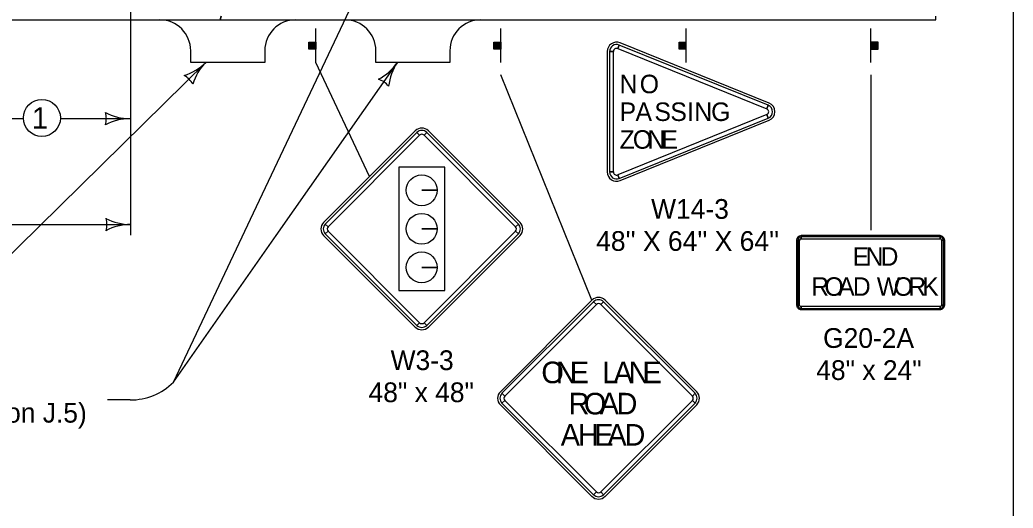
# Model space of a CAD drawing. Extents: x -2134934 to -2122394, y -2139046 to -2137036.
# Drawn here: x -2132604 to -2131799, y -2138064 to -2137668 of the extents above; entities that cross this region are included whole.
import ezdxf

# ---------------------------------------------------------------- set-up
doc = ezdxf.new("R2010")
doc.units = 0
for name, color, linetype in [('Barrier', 7, 'Continuous'), ('BridgeSuperStructureExisting', 7, 'Continuous'), ('Default', 7, 'Continuous'), ('DsnShtPlotIdentification', 7, 'Continuous'), ('DsnShtPlotShape', 7, 'Continuous')]:
    doc.layers.add(name, color=color, linetype=linetype)

msp = doc.modelspace()

# ---------------------------------------------------------------- linework, layer by layer
at = {"layer": 'Barrier'}
for p, q in [((-2132119.84, -2137691.45), (-2132118.67, -2137688.56)), ((-2131997.15, -2137735.69), (-2132117.97, -2137686.82)), ((-2132128.28, -2137693.77), (-2132128.28, -2137791.52)), ((-2132126.41, -2137693.77), (-2132123.28, -2137693.77)), ((-2131997.85, -2137737.43), (-2131999.02, -2137740.33)), ((-2131999.02, -2137744.96), (-2131997.85, -2137747.86)), ((-2132117.97, -2137798.48), (-2131997.15, -2137749.6)), ((-2132283.85, -2137758.12), (-2132358.09, -2137832.37)), ((-2132282.52, -2137759.45), (-2132280.31, -2137761.66)), ((-2132276.78, -2137761.66), (-2132274.57, -2137759.45)), ((-2132198.99, -2137832.37), (-2132273.24, -2137758.12)), ((-2132123.28, -2137791.52), (-2132126.41, -2137791.52)), ((-2132118.67, -2137796.74), (-2132119.84, -2137793.84)), ((-2132266.14, -2137806.34), (-2132278.64, -2137806.34)), ((-2132278.64, -2137806.34), (-2132266.14, -2137806.34)), ((-2132354.56, -2137835.9), (-2132356.77, -2137833.69)), ((-2132200.32, -2137833.69), (-2132202.53, -2137835.9)), ((-2132358.09, -2137842.98), (-2132283.85, -2137917.22)), ((-2132356.77, -2137841.65), (-2132354.56, -2137839.44)), ((-2132266.14, -2137837.59), (-2132278.64, -2137837.59)), ((-2132278.64, -2137837.59), (-2132266.14, -2137837.59)), ((-2132273.24, -2137917.22), (-2132198.99, -2137842.98)), ((-2132202.53, -2137839.44), (-2132200.32, -2137841.65)), ((-2131858.66, -2137843.14), (-2131971.16, -2137843.14)), ((-2131971.16, -2137845.64), (-2131971.16, -2137844.08)), ((-2131858.66, -2137844.08), (-2131858.66, -2137845.64)), ((-2131974.91, -2137846.89), (-2131974.91, -2137899.39)), ((-2131973.97, -2137846.89), (-2131972.41, -2137846.89)), ((-2131857.41, -2137846.89), (-2131855.85, -2137846.89)), ((-2131854.91, -2137899.39), (-2131854.91, -2137846.89)), ((-2132266.14, -2137868.84), (-2132278.64, -2137868.84)), ((-2132278.64, -2137868.84), (-2132266.14, -2137868.84)), ((-2132140.68, -2137895.4), (-2132214.93, -2137969.64)), ((-2132139.36, -2137896.72), (-2132137.15, -2137898.93)), ((-2132133.61, -2137898.93), (-2132131.4, -2137896.72)), ((-2132055.83, -2137969.64), (-2132130.08, -2137895.4)), ((-2131972.41, -2137899.39), (-2131973.97, -2137899.39)), ((-2131971.16, -2137902.2), (-2131971.16, -2137900.64)), ((-2131858.66, -2137900.64), (-2131858.66, -2137902.2)), ((-2131855.85, -2137899.39), (-2131857.41, -2137899.39)), ((-2131971.16, -2137903.14), (-2131858.66, -2137903.14)), ((-2132280.31, -2137913.69), (-2132282.52, -2137915.9)), ((-2132274.57, -2137915.9), (-2132276.78, -2137913.69)), ((-2132211.4, -2137973.18), (-2132213.6, -2137970.97)), ((-2132057.16, -2137970.97), (-2132059.37, -2137973.18)), ((-2132214.93, -2137980.25), (-2132140.68, -2138054.5)), ((-2132213.6, -2137978.92), (-2132211.4, -2137976.71)), ((-2132130.08, -2138054.5), (-2132055.83, -2137980.25)), ((-2132059.37, -2137976.71), (-2132057.16, -2137978.92)), ((-2132137.15, -2138050.96), (-2132139.36, -2138053.17)), ((-2132131.4, -2138053.17), (-2132133.61, -2138050.96))]:
    msp.add_line(p, q, dxfattribs=at)
for points in [[(-2131997.85, -2137737.43), (-2132118.67, -2137688.56), (-2132119.84, -2137691.45), (-2131999.02, -2137740.33), (-2131997.85, -2137737.43)], [(-2132126.41, -2137693.77), (-2132126.41, -2137791.52), (-2132123.28, -2137791.52), (-2132123.28, -2137693.77), (-2132126.41, -2137693.77)], [(-2132118.67, -2137796.74), (-2131997.85, -2137747.86), (-2131999.02, -2137744.96), (-2132119.84, -2137793.84), (-2132118.67, -2137796.74)], [(-2132282.52, -2137759.45), (-2132356.77, -2137833.69), (-2132354.56, -2137835.9), (-2132280.31, -2137761.66), (-2132282.52, -2137759.45)], [(-2132200.32, -2137833.69), (-2132274.57, -2137759.45), (-2132276.78, -2137761.66), (-2132202.53, -2137835.9), (-2132200.32, -2137833.69)], [(-2132259.81, -2137787.73), (-2132297.28, -2137787.73), (-2132297.28, -2137887.62), (-2132259.81, -2137887.62), (-2132259.81, -2137787.73)], [(-2132356.77, -2137841.65), (-2132282.52, -2137915.9), (-2132280.31, -2137913.69), (-2132354.56, -2137839.44), (-2132356.77, -2137841.65)], [(-2132274.57, -2137915.9), (-2132200.32, -2137841.65), (-2132202.53, -2137839.44), (-2132276.78, -2137913.69), (-2132274.57, -2137915.9)], [(-2131858.66, -2137844.08), (-2131971.16, -2137844.08), (-2131971.16, -2137845.64), (-2131858.66, -2137845.64), (-2131858.66, -2137844.08)], [(-2131973.97, -2137846.89), (-2131973.97, -2137899.39), (-2131972.41, -2137899.39), (-2131972.41, -2137846.89), (-2131973.97, -2137846.89)], [(-2131855.85, -2137899.39), (-2131855.85, -2137846.89), (-2131857.41, -2137846.89), (-2131857.41, -2137899.39), (-2131855.85, -2137899.39)], [(-2132139.36, -2137896.72), (-2132213.6, -2137970.97), (-2132211.4, -2137973.18), (-2132137.15, -2137898.93), (-2132139.36, -2137896.72)], [(-2132057.16, -2137970.97), (-2132131.4, -2137896.72), (-2132133.61, -2137898.93), (-2132059.37, -2137973.18), (-2132057.16, -2137970.97)], [(-2131971.16, -2137902.2), (-2131858.66, -2137902.2), (-2131858.66, -2137900.64), (-2131971.16, -2137900.64), (-2131971.16, -2137902.2)], [(-2132213.6, -2137978.92), (-2132139.36, -2138053.17), (-2132137.15, -2138050.96), (-2132211.4, -2137976.71), (-2132213.6, -2137978.92)], [(-2132131.4, -2138053.17), (-2132057.16, -2137978.92), (-2132059.37, -2137976.71), (-2132133.61, -2138050.96), (-2132131.4, -2138053.17)]]:
    msp.add_lwpolyline(points, close=True, dxfattribs=at)
for centre in [(-2132278.64, -2137806.34), (-2132278.64, -2137837.59), (-2132278.64, -2137868.84)]:
    msp.add_circle(centre, 12.5, dxfattribs=at)
for centre, radius, start, end in [((-2132120.78, -2137693.77), 7.5, 67.97571, 179.99985), ((-2132120.78, -2137693.77), 5.62, 67.97571, 179.99985), ((-2132120.78, -2137693.77), 2.5, 67.97571, 179.99985), ((-2131999.96, -2137742.65), 2.5, 292.02456, 67.97541), ((-2131999.96, -2137742.65), 5.62, 292.02456, 67.97541), ((-2131999.96, -2137742.65), 7.5, 292.02456, 67.97598), ((-2132278.54, -2137763.43), 7.5, 44.99999, 134.99974), ((-2132278.54, -2137763.43), 5.62, 44.99999, 134.99974), ((-2132278.54, -2137763.43), 2.5, 44.99999, 134.99974), ((-2132120.78, -2137791.52), 7.5, 179.99985, 292.02456), ((-2132120.78, -2137791.52), 5.62, 179.99985, 292.02456), ((-2132120.78, -2137791.52), 2.5, 179.99985, 292.02456), ((-2132352.79, -2137837.67), 7.5, 134.99974, 224.99995), ((-2132352.79, -2137837.67), 5.62, 134.99974, 224.99995), ((-2132352.79, -2137837.67), 2.5, 134.99974, 224.99995), ((-2132204.3, -2137837.67), 2.5, 315.00016, 44.9998), ((-2132204.3, -2137837.67), 5.62, 315.00016, 44.9998), ((-2132204.3, -2137837.67), 7.5, 315.00016, 44.9998), ((-2131971.16, -2137846.89), 3.75, 90.00021, 179.99985), ((-2131971.16, -2137846.89), 2.81, 90.00021, 179.99985), ((-2131858.66, -2137846.89), 3.75, 0, 90.00021), ((-2131858.66, -2137846.89), 2.81, 0, 90.00021), ((-2131971.16, -2137846.89), 1.25, 90.00021, 179.99985), ((-2131858.66, -2137846.89), 1.25, 0, 90.00021), ((-2132135.38, -2137900.7), 7.5, 44.99999, 134.99974), ((-2132135.38, -2137900.7), 5.62, 44.99999, 134.99974), ((-2132135.38, -2137900.7), 2.5, 44.99999, 134.99974), ((-2131971.16, -2137899.39), 3.75, 179.99985, 270.00006), ((-2131971.16, -2137899.39), 2.81, 179.99985, 270.00006), ((-2131971.16, -2137899.39), 1.25, 179.99985, 270.00006), ((-2131858.66, -2137899.39), 3.75, 270.00006, 0.00027), ((-2131858.66, -2137899.39), 2.81, 270.00006, 0.00027), ((-2131858.66, -2137899.39), 1.25, 270.00006, 0.00027), ((-2132278.54, -2137911.92), 7.5, 224.99995, 315.00016), ((-2132278.54, -2137911.92), 5.62, 224.99995, 315.00016), ((-2132278.54, -2137911.92), 2.5, 224.99995, 315.00016), ((-2132209.63, -2137974.95), 7.5, 134.99974, 224.99995), ((-2132209.63, -2137974.95), 5.62, 134.99974, 224.99995), ((-2132209.63, -2137974.95), 2.5, 134.99974, 224.99995), ((-2132061.14, -2137974.95), 2.5, 315.00016, 44.9998), ((-2132061.14, -2137974.95), 5.62, 315.00016, 44.9998), ((-2132061.14, -2137974.95), 7.5, 315.00016, 44.9998), ((-2132135.38, -2138049.19), 5.62, 224.99995, 315.00016), ((-2132135.38, -2138049.19), 2.5, 224.99995, 315.00016), ((-2132135.38, -2138049.19), 7.5, 224.99995, 315.00016)]:
    msp.add_arc(centre, radius, start, end, dxfattribs=at)
at = {"layer": 'BridgeSuperStructureExisting'}
for p, q in [((-2132414.88, -2137824.64), (-2132275.76, -2137530.07)), ((-2132514.45, -2137842.77), (-2132514.45, -2137605.16)), ((-2132490.81, -2137668.16), (-2132380.81, -2137668.16)), ((-2132364.45, -2137702.66), (-2132364.45, -2137675.16)), ((-2132340.81, -2137668.16), (-2132230.81, -2137668.16)), ((-2132214.45, -2137702.66), (-2132214.45, -2137675.16)), ((-2132064.45, -2137702.66), (-2132064.45, -2137675.16)), ((-2131914.64, -2137702.66), (-2131914.64, -2137675.16)), ((-2132369.77, -2137691.8), (-2132369.77, -2137686.21)), ((-2132369.45, -2137686.21), (-2132369.45, -2137691.8)), ((-2132369.23, -2137691.8), (-2132369.23, -2137686.21)), ((-2132368.91, -2137686.21), (-2132368.91, -2137691.8)), ((-2132368.68, -2137691.8), (-2132368.7, -2137686.21)), ((-2132368.27, -2137686.21), (-2132368.25, -2137691.8)), ((-2132368.05, -2137691.8), (-2132368.05, -2137686.21)), ((-2132367.62, -2137686.21), (-2132367.62, -2137691.8)), ((-2132367.24, -2137691.8), (-2132367.24, -2137686.21)), ((-2132366.92, -2137686.21), (-2132366.9, -2137691.8)), ((-2132366.7, -2137691.8), (-2132366.7, -2137686.21)), ((-2132366.43, -2137686.21), (-2132366.43, -2137691.8)), ((-2132366.1, -2137691.8), (-2132366.1, -2137686.21)), ((-2132365.89, -2137686.21), (-2132365.89, -2137691.8)), ((-2132365.67, -2137691.8), (-2132365.67, -2137686.21)), ((-2132365.4, -2137686.21), (-2132365.4, -2137691.8)), ((-2132365.14, -2137691.8), (-2132365.14, -2137686.21)), ((-2132364.86, -2137686.21), (-2132364.86, -2137691.8)), ((-2132219.77, -2137691.8), (-2132219.77, -2137686.21)), ((-2132219.45, -2137686.21), (-2132219.45, -2137691.8)), ((-2132219.23, -2137691.8), (-2132219.23, -2137686.21)), ((-2132218.91, -2137686.21), (-2132218.91, -2137691.8)), ((-2132218.69, -2137691.8), (-2132218.7, -2137686.21)), ((-2132218.27, -2137686.21), (-2132218.25, -2137691.8)), ((-2132218.05, -2137691.8), (-2132218.05, -2137686.21)), ((-2132217.62, -2137686.21), (-2132217.62, -2137691.8)), ((-2132217.24, -2137691.8), (-2132217.24, -2137686.21)), ((-2132216.92, -2137686.21), (-2132216.9, -2137691.8)), ((-2132216.7, -2137691.8), (-2132216.7, -2137686.21)), ((-2132216.43, -2137686.21), (-2132216.43, -2137691.8)), ((-2132216.1, -2137691.8), (-2132216.1, -2137686.21)), ((-2132215.89, -2137686.21), (-2132215.89, -2137691.8)), ((-2132215.67, -2137691.8), (-2132215.67, -2137686.21)), ((-2132215.4, -2137686.21), (-2132215.4, -2137691.8)), ((-2132215.14, -2137691.8), (-2132215.14, -2137686.21)), ((-2132214.86, -2137686.21), (-2132214.86, -2137691.8)), ((-2132069.77, -2137691.8), (-2132069.77, -2137686.21)), ((-2132069.45, -2137686.21), (-2132069.45, -2137691.8)), ((-2132069.23, -2137691.8), (-2132069.23, -2137686.21)), ((-2132068.91, -2137686.21), (-2132068.91, -2137691.8)), ((-2132068.69, -2137691.8), (-2132068.7, -2137686.21)), ((-2132068.27, -2137686.21), (-2132068.25, -2137691.8)), ((-2132068.05, -2137691.8), (-2132068.05, -2137686.21)), ((-2132067.62, -2137686.21), (-2132067.62, -2137691.8)), ((-2132067.24, -2137691.8), (-2132067.24, -2137686.21)), ((-2132066.92, -2137686.21), (-2132066.9, -2137691.8)), ((-2132066.7, -2137691.8), (-2132066.7, -2137686.21)), ((-2132066.43, -2137686.21), (-2132066.43, -2137691.8)), ((-2132066.1, -2137691.8), (-2132066.1, -2137686.21)), ((-2132065.89, -2137686.21), (-2132065.89, -2137691.8)), ((-2132065.67, -2137691.8), (-2132065.67, -2137686.21)), ((-2132065.4, -2137686.21), (-2132065.4, -2137691.8)), ((-2132065.14, -2137691.8), (-2132065.14, -2137686.21)), ((-2132064.86, -2137686.21), (-2132064.86, -2137691.8)), ((-2131914.22, -2137686.21), (-2131914.22, -2137691.8)), ((-2131913.94, -2137691.8), (-2131913.94, -2137686.21)), ((-2131913.68, -2137686.21), (-2131913.68, -2137691.8)), ((-2131913.42, -2137691.8), (-2131913.42, -2137686.21)), ((-2131913.19, -2137686.21), (-2131913.19, -2137691.8)), ((-2131912.99, -2137691.8), (-2131912.99, -2137686.21)), ((-2131912.65, -2137686.21), (-2131912.65, -2137691.8)), ((-2131912.39, -2137691.8), (-2131912.39, -2137686.21)), ((-2131912.16, -2137686.21), (-2131912.18, -2137691.8)), ((-2131911.84, -2137691.8), (-2131911.84, -2137686.21)), ((-2131911.47, -2137686.21), (-2131911.47, -2137691.8)), ((-2131911.04, -2137691.8), (-2131911.04, -2137686.21)), ((-2131910.81, -2137686.21), (-2131910.83, -2137691.8)), ((-2131910.4, -2137691.8), (-2131910.38, -2137686.21)), ((-2131910.17, -2137686.21), (-2131910.17, -2137691.8)), ((-2131909.85, -2137691.8), (-2131909.85, -2137686.21)), ((-2131909.63, -2137686.21), (-2131909.63, -2137691.8)), ((-2131909.31, -2137691.8), (-2131909.31, -2137686.21)), ((-2132641.72, -2137887.94), (-2132453.59, -2137702.65)), ((-2132396.52, -2137843), (-2132298.35, -2137702.65)), ((-2132320.97, -2137795.25), (-2132364.45, -2137702.66)), ((-2132140.68, -2137895.4), (-2132214.45, -2137712.66)), ((-2131914.45, -2137838.71), (-2131914.45, -2137712.66)), ((-2132714.94, -2137748.23), (-2132601.37, -2137748.23)), ((-2132571.38, -2137748.23), (-2132514.94, -2137748.23)), ((-2132479.75, -2137962), (-2132414.88, -2137824.64)), ((-2132739.17, -2137834.09), (-2132514.45, -2137834.09)), ((-2132479.75, -2137962), (-2132396.52, -2137843)), ((-2132514.83, -2137976.38), (-2132533.29, -2137976.38))]:
    msp.add_line(p, q, dxfattribs=at)
for points in [[(-2132364.54, -2137686.21), (-2132364.54, -2137691.84), (-2132370.17, -2137691.84), (-2132370.17, -2137686.21)], [(-2132214.54, -2137686.21), (-2132214.54, -2137691.84), (-2132220.17, -2137691.84), (-2132220.17, -2137686.21)], [(-2132064.54, -2137686.21), (-2132064.54, -2137691.84), (-2132070.17, -2137691.84), (-2132070.17, -2137686.21)], [(-2131914.54, -2137686.21), (-2131914.54, -2137691.84), (-2131908.92, -2137691.84), (-2131908.92, -2137686.21)]]:
    msp.add_lwpolyline(points, close=True, dxfattribs=at)
for points in [[(-2132405.81, -2137693.16), (-2132405.81, -2137702.65), (-2132465.81, -2137702.65), (-2132465.81, -2137693.16)], [(-2132255.81, -2137693.16), (-2132255.81, -2137702.65), (-2132315.81, -2137702.65), (-2132315.81, -2137693.16)]]:
    msp.add_lwpolyline(points, dxfattribs=at)
msp.add_circle((-2132586.38, -2137747.73), 15, dxfattribs=at)
for centre, radius, start, end in [((-2132490.81, -2137693.16), 25, 0, 90), ((-2132380.81, -2137693.16), 25, 90, 180), ((-2132340.81, -2137693.16), 25, 0, 90), ((-2132230.81, -2137693.16), 25, 90, 180), ((-2132550.57, -2137748.23), 16.42, 342.26665, 17.73335), ((-2132514.94, -2137705.73), 42.5, 241.92751, 270), ((-2132514.94, -2137790.73), 42.5, 90, 118.07249), ((-2132514.83, -2137926.38), 50, 270, 314.56349)]:
    msp.add_arc(centre, radius, start, end, dxfattribs=at)
at = {"layer": 'Default'}
msp.add_lwpolyline([(-2134934.44, -2137035.95), (-2131799.45, -2137035.95), (-2131799.45, -2139045.94), (-2134934.44, -2139045.94)], close=True, dxfattribs=at)
at = {"layer": 'DsnShtPlotIdentification'}
for p, q in [((-2132442.06, -2137668.16), (-2132441.05, -2137665.16)), ((-2132441.05, -2137665.16), (-2132442.06, -2137668.16)), ((-2131861.99, -2137668.16), (-2131861.99, -2137665.16)), ((-2131861.99, -2137668.16), (-2131861.99, -2137665.16)), ((-2133364.44, -2137668.16), (-2131861.99, -2137668.16)), ((-2132714.94, -2137668.16), (-2132442.06, -2137668.16)), ((-2132442.06, -2137668.16), (-2131861.99, -2137668.16))]:
    msp.add_line(p, q, dxfattribs=at)
at = {"layer": 'DsnShtPlotShape'}
for centre, radius, start, end in [((-2132483.78, -2137672.74), 42.5, 287.19716, 315.26965), ((-2132423.4, -2137732.56), 42.5, 135.26965, 163.34214), ((-2132333.48, -2137678.72), 42.5, 297.66406, 325.73655), ((-2132263.23, -2137726.58), 42.5, 145.73655, 173.80904), ((-2132478.67, -2137727.96), 16.42, 27.53629, 63.003), ((-2132318.42, -2137732.1), 16.42, 38.0032, 73.4699), ((-2132550.08, -2137834.09), 16.42, 342.26665, 17.73335), ((-2132514.45, -2137791.59), 42.5, 241.92751, 270), ((-2132514.45, -2137876.59), 42.5, 90, 118.07249)]:
    msp.add_arc(centre, radius, start, end, dxfattribs=at)

# ---------------------------------------------------------------- texts
at = {"layer": 'Barrier'}
for s, height, p in [('N', 15, (-2132118.31, -2137727.65)), ('O', 15, (-2132101.97, -2137727.65)), ('P', 15, (-2132118.31, -2137750.15)), ('A', 15, (-2132105.42, -2137750.15)), ('S', 15, (-2132090.07, -2137750.15)), ('S', 15, (-2132077.18, -2137750.15)), ('I', 15, (-2132063.59, -2137750.15)), ('N', 15, (-2132057.73, -2137750.15)), ('G', 15, (-2132044.13, -2137750.15)), ('Z', 15, (-2132118.31, -2137772.65)), ('O', 15, (-2132107.58, -2137772.65)), ('N', 15, (-2132095.75, -2137772.65)), ('E', 15, (-2132084.38, -2137772.65)), ('W14-3', 16, (-2132092.77, -2137829.48)), ("48'' X 64'' X 64''", 16, (-2132137.26, -2137855.47)), ('E', 15, (-2131929.58, -2137867.51)), ('N', 15, (-2131918.96, -2137867.51)), ('D', 15, (-2131906.88, -2137867.51)), ('R', 15, (-2131963.05, -2137891.89)), ('O', 15, (-2131952.36, -2137891.89)), ('A', 15, (-2131941.21, -2137891.89)), ('D', 15, (-2131929.35, -2137891.89)), ('W', 15, (-2131909.9, -2137891.89)), ('O', 15, (-2131896.16, -2137891.89)), ('R', 15, (-2131884.4, -2137891.89)), ('K', 15, (-2131873.1, -2137891.89)), ('G20-2A', 16, (-2131953.44, -2137934.14)), ('W3-3', 16, (-2132303.84, -2137952.14)), ('O', 17.5, (-2132181.67, -2137962.76)), ('N', 17.5, (-2132169.89, -2137962.76)), ('E', 17.5, (-2132158.66, -2137962.76)), ('L', 17.5, (-2132132.41, -2137962.76)), ('A', 17.5, (-2132123.22, -2137962.76)), ('N', 17.5, (-2132110.95, -2137962.76)), ('E', 17.5, (-2132099.72, -2137962.76)), ('48" x 24"', 16, (-2131958.97, -2137960.14)), ('48" x 48"', 16, (-2132321.71, -2137978.14)), ('R', 17.5, (-2132159.56, -2137988.07)), ('O', 17.5, (-2132147.27, -2137988.07)), ('A', 17.5, (-2132134.43, -2137988.07)), ('D', 17.5, (-2132120.78, -2137988.07)), ('A', 17.5, (-2132166, -2138013.38)), ('H', 17.5, (-2132152.13, -2138013.38)), ('E', 17.5, (-2132138.91, -2138013.38)), ('A', 17.5, (-2132128.2, -2138013.38)), ('D', 17.5, (-2132114.34, -2138013.38))]:
    msp.add_text(s, height=height, dxfattribs=at).set_placement(p)
at = {"layer": 'BridgeSuperStructureExisting'}
for s, height, p in [('1', 17.5, (-2132594.44, -2137756.48)), ('(See Indigo Ave Advanced Signing on J.5)', 16, (-2132952.04, -2137994.73))]:
    msp.add_text(s, height=height, dxfattribs=at).set_placement(p)

doc.saveas('drawing.dxf')
